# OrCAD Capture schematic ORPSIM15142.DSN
size A
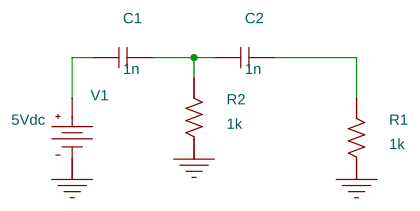
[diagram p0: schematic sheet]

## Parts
C1  1n  [CK05]
C2  1n  [CK05]
R1  1k  [RC05]
R2  1k  [RC05]
V1  VDC

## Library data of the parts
C1 C2 = C
R1 R2 = R
V1 = VDC: DC: 5Vdc

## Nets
0: R1.1 R2.1 V1.1(-)
N00108: C1.1 V1.0(+)
N00115: C1.2 C2.1 R2.2
N00119: C2.2 R1.2
